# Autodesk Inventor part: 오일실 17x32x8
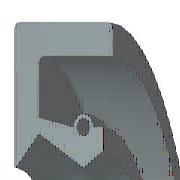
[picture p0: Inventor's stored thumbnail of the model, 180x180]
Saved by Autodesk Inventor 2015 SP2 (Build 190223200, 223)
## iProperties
IsCustomPart: 1
Created: 2009-02
Part Number: 오일실 17x32x8
Material: 고무
Description: 오일-실
Document SubType Name: Modeling
Standard: KS B 2804
Designer: 한국산업디자인학원
Standards Organization: KS
Language: ko-KR
Size Designation: D - 17 32 8
Categories: <MemberInstance><Categories><Category DisplayName="샤프트 부품" InternalName="7f7aeb1f-a693-4053-b835-cee3144e0d98" Mnemonic="SHFT"><Category DisplayName="실링" Intern
Density: 0.93 g/cm^3
Appearance: 고무 - 검은색 - 버전 1.1
Author: 한국산업디자인학원
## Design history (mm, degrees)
revolve "본체" stored, may be unused: angle "d17" = 90 deg
revolve "스프링1" stored, may be unused: angle "d18" = 90 deg
body "Solid1"
sketch "스케치1"
  geometry: L1 (0, 16)-(8, 16); L2 (8, 14.25)-(1.75, 14.25); L3 (1.75, 10.25)-(4.9, 8.5); L4 (4.9, 8.5)-(0, 8.5); L5 (0, 0)-(9.586, 0) reference; L6 (4.9, 8.5)-(6.3, 9.375); L7 (0, 18)-(0, -3) reference; L8 (-1.941, 0)-(11.507, 0) reference; L9 (4.2, 10.6)-(1.75, 11.21); L10 (1.75, 11.21)-(1.75, 14.25); L11 (0, 16)-(0, 8.588); L12 (4.9, 8.5)-(0, 8.5); L13 (1.75, 10.25)-(0.152, 8.528); L14 (8, 16)-(8, 14.25); L15 (5.6, 10.6)-(6.3, 10.6); L16 (6.3, 10.6)-(6.3, 9.375); C1 r 0.455 at (4.9, 10.6); A1 r 0.7 centre (4.9, 10.6) between (5.6, 10.6) and (4.2, 10.6); A2 r 0.088 centre (0.088, 8.588) between (0, 8.588) and (0.152, 8.528); 1 further point
  constraints: 28 end point, 5 horizontal alignment, 5 point on line, 4 point on circle, 4 vertical alignment, 3 centre point, 3 tangent, 2 collinear, 2 horizontal, 2 perpendicular, 1 coincident, 1 parallel
  dimensions: "d0" = 32 diameter of L1 L5 (= SD2); "d1" = 1.75 distance of L1.end L2.start (= SD); "d2" = 0.91 diameter of C1 (= SPDI); "d3" = 1.4 diameter of A1 (= SPDA); "d4" = 17 diameter of L3.end L5 (= NND); "d5" = 20.5 diameter of L3.start L5 (= TKDM); "d7" = 22.42 diameter of L9.end L5 (= TKDM + 0.24 x SWDT); "d8" = 1.75 distance between parallel lines of L11 L10 (= SD); "d9" = 4.9 distance from line of L11 C1.centre (= SPDST); "d10" = 21.2 diameter of C1.centre L5 (= HLDM); "d11" = 0.0875 radius of A2 (= 0.25 x LAB); "d12" = 6.3 distance between parallel lines of L11 L16 (= SDI); "d13" = 18.75 diameter of L6.end L5 (= ABDM); "d14" = 8 distance from line of L11 L1.end (= SWDT)
fillet "모깎기1" dims "d6" = 0.3 (= RR)
other parameters: "SD2" = 32 [user parameter; used in 1 equation term], "SWDT" = 8 [user parameter; used in 2 equation terms], "RR" = 0.3 [user parameter; used in 1 equation term], "SD" = 1.75 [user parameter; used in 2 equation terms], "NND" = 17 [user parameter; used in 1 equation term], "SPDA" = 1.4 [user parameter; used in 1 equation term], "SPDI" = 0.91 [user parameter; used in 1 equation term], "TKDM" = 20.5 [user parameter; used in 2 equation terms], "HLDM" = 21.2 [user parameter; used in 1 equation term], "ABDM" = 18.75 [user parameter; used in 1 equation term], "SDI" = 6.3 [user parameter; used in 1 equation term], "SPDST" = 4.9 [user parameter; used in 1 equation term], "LAB" = 0.35 [user parameter; used in 1 equation term], "d15" = 0, "d16" = 0, "d19" = 0
